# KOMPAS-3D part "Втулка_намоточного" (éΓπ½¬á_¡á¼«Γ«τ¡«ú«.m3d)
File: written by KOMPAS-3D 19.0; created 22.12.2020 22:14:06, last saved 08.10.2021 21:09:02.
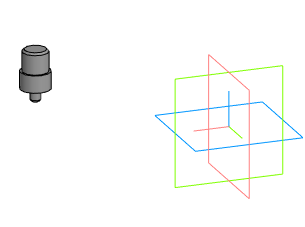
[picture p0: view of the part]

Document properties: Автор: Agent Smith; Организация: Pda-nn; Комментарий: Свободный софт !; Полное имя файла: D:\3D_print\3D проекты Компас 3D\Халява Projects 5\Втулка_намоточного.m3d

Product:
- Part/product: Втулка_намоточного
    Материал: Полиэтилен 20108-001 ГОСТ 16338-85 (density 949 kg/m3)
    Масса: 0.00235951

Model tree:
1. Эскиз:1  (with: Элемент выдавливания:1)
2. Элемент выдавливания:1
     Расстояние 2 = 5
3. Эскиз:2  (with: Элемент выдавливания:1)
4. Элемент выдавливания:2
     Расстояние 1 = 1
5. Эскиз:3  (with: Цилиндр (Шестерня цилиндрическая с внешними зубьями):1, Элемент выдавливания:7)
6. Элемент выдавливания:3
     Расстояние 2 = 10
7. Эскиз:4  (with: Элемент выдавливания:3)
8. Элемент выдавливания:4  (with: Элемент выдавливания:2)
     Расстояние 1 = 8
9. Фаска:1  (with: Элемент выдавливания:1)
     Угол = 45; Длина 1 = 1; Длина 2 = 1
10. Фаска:2  (with: Элемент выдавливания:3)
     Угол = 45; Длина 1 = 1; Длина 2 = 1

Referenced files in D:\3D_print\3D проекты Компас 3D\Халява Projects_3\: Намоточный станок - ver.3.1.a3d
